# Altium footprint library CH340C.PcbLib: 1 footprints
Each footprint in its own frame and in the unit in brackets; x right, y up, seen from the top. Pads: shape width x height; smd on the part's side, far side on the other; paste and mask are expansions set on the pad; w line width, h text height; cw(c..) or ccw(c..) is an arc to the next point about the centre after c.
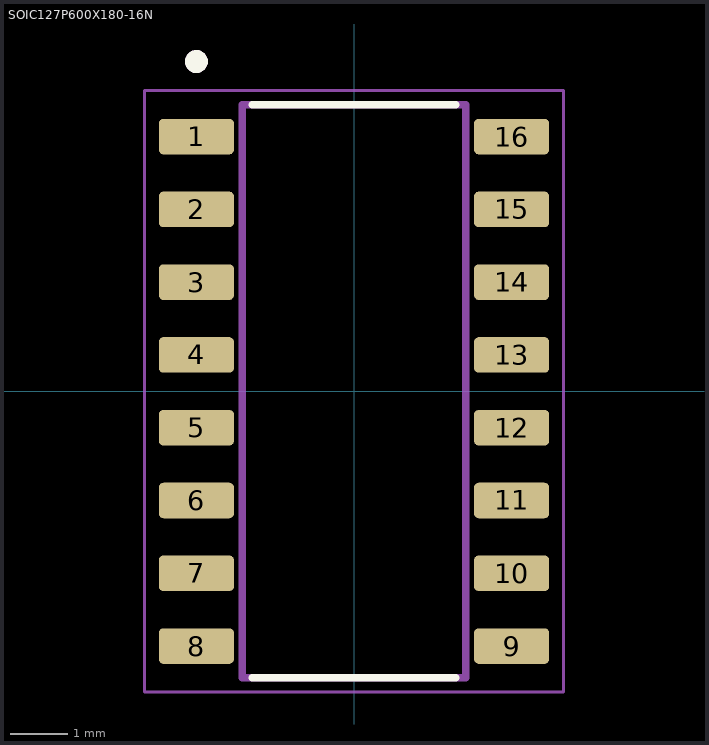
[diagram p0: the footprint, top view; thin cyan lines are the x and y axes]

## SOIC127P600X180-16N [mm]
height 1.8
pads (16):
  rrect25% 1.31x0.62 smd: 1(-2.75,4.445) 2(-2.75,3.175) 3(-2.75,1.905) 4(-2.75,0.635) 5(-2.75,-0.635) 6(-2.75,-1.905) 7(-2.75,-3.175) 8(-2.75,-4.445) 9(2.75,-4.445) 10(2.75,-3.175) 11(2.75,-1.905) 12(2.75,-0.635) 13(2.75,0.635) 14(2.75,1.905) 15(2.75,3.175) 16(2.75,4.445)
Top Overlay:
  circle w0.2: c-2.75,5.755 r0.1
  lines w0.127: -1.775,-5 1.775,-5 -1.775,-5 ; -1.775,5 1.775,5 -1.775,5
Mechanical 13:
  circle w0.2: c-2.75,5.755 r0.1
  lines w0.127: -1.95,-5 -1.95,5 1.95,5 1.95,-5 -1.95,-5
Mechanical 15:
  lines w0.05: -3.655,-5.25 3.655,-5.25 3.655,5.25 -3.655,5.25 -3.655,-5.25
3D body "step_temp.STEP": height 1.8, standoff 0, extent -3,-5 3,5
